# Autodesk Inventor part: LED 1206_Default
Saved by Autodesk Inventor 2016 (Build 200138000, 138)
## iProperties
Created: 2012-01
Part Number: LED 1206_Default
Document SubType Name: Modeling
Designer: Trevor
Density: 1 g/cm^3
Material: Generic
Appearance: Default
Author: Trevor
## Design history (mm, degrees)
feature "Base1"
feature "Base2"
node "Imported1"
node "Imported2"
